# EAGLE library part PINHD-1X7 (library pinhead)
PIN HEADER
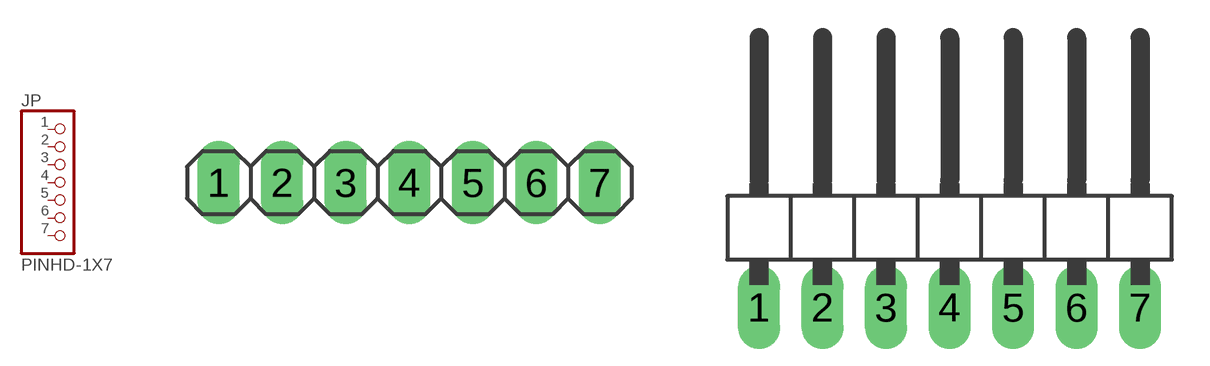
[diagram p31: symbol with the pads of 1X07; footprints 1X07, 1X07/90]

Designator prefix JP

## PINHD-1X7  [1X07]
1  1  pas
2  2  pas
3  3  pas
4  4  pas
5  5  pas
6  6  pas
7  7  pas

## PINHD-1X7/90  [1X07/90]
Pads as for 1X07

## Footprint 1X07 (pad centres in mm)
PIN HEADER
drill 1.016 pad 1.67 long: 1 -7.62,0; 2 -5.08,0; 3 -2.54,0; 4 0,0; 5 2.54,0; 6 5.08,0; 7 7.62,0

## Footprint 1X07/90 (pad centres in mm)
PIN HEADER
drill 1.016 pad 1.67 long: 1 -7.62,-3.81; 2 -5.08,-3.81; 3 -2.54,-3.81; 4 0,-3.81; 5 2.54,-3.81; 6 5.08,-3.81; 7 7.62,-3.81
